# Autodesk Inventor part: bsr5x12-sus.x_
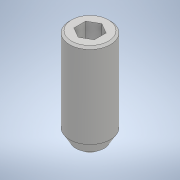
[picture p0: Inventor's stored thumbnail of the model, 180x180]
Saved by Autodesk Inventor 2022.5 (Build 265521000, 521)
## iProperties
Created: 2020-01
Part Number: bsr5x12-sus.x_
Material: 一般
Document SubType Name: Modeling
Designer: ImaoCorp
Density: 1 g/cm^3
Appearance: 既定
Sending System: SOLIDWORKS 2018-2018316
MC: AMD64
MC_MODEL: Intel64 Family 6 Model 60 Stepping 3, GenuineIntel
OS: Windows_NT
FRU: Parasolid Version 30.0, build 310,  6- 8-2018
FORMAT: text
GUISE: transmit
KEY: bsr5x12-sus
FILE: bsr5x12-sus.x_t
DATE: Thu Jan 23 16:47:22 2020
Author: ImaoCorp
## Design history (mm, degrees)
feature "Base1"
node "ソリッド1"
